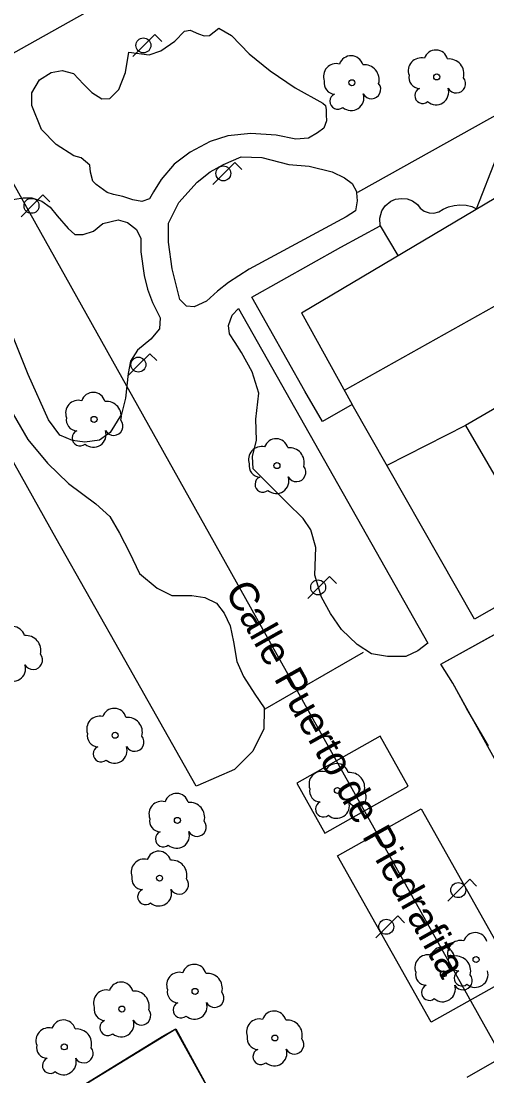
# Model space of a CAD drawing. Extents: x 282771 to 285132, y 4823109 to 4825496.
# Drawn here: x 283637.2 to 283677, y 4823316.2 to 4823406.2 of the extents above; entities that cross this region are included whole.
import ezdxf

# ---------------------------------------------------------------- set-up
doc = ezdxf.new("R2010")
doc.units = 0
for name, color, linetype in [('ACERA-INTERIOR', 7, 'Continuous'), ('ARBOL', 7, 'Continuous'), ('CALLE-EJE', 7, 'Continuous'), ('CALLE-TEXTO', 7, 'Continuous'), ('COLEGIO-AREA', 7, 'Continuous'), ('EDIFICIO', 7, 'Continuous'), ('FAROLA', 7, 'Continuous'), ('MEDIANERA', 7, 'Continuous'), ('PARQUE-JARDIN-AREA', 7, 'Continuous'), ('ZONA-VERDE', 7, 'Continuous')]:
    doc.layers.add(name, color=color, linetype=linetype)

msp = doc.modelspace()

# ---------------------------------------------------------------- linework, layer by layer
at = {"layer": 'ACERA-INTERIOR'}
for points in [[(283705.471, 4823369.905), (283686.968, 4823403.313), (283665.899, 4823391.566)], [(283658.036, 4823347.525), (283666.435, 4823352.366)]]:
    msp.add_lwpolyline(points, dxfattribs=at)
at = {"layer": 'ARBOL'}
for centre in [(283665.427, 4823400.948), (283672.673, 4823401.441), (283643.407, 4823372.22), (283659.026, 4823368.273), (283645.203, 4823345.261), (283664.193, 4823340.551), (283650.523, 4823338.001), (283649.003, 4823333.071), (283676.033, 4823326.126), (283673.243, 4823324.901), (283652.033, 4823323.411), (283645.783, 4823321.901), (283658.853, 4823319.431), (283640.863, 4823318.671)]:
    msp.add_circle(centre, 0.255, dxfattribs=at)
for centre, radius, start, end in [((283665.357, 4823402.208), 1.038, 15.64228, 161.38435), ((283671.343, 4823401.971), 1.097, 75.4318, 200.55608), ((283672.603, 4823402.701), 1.038, 15.64228, 161.38435), ((283673.733, 4823401.701), 1.272, 345.03273, 95.79925), ((283664.097, 4823401.478), 1.097, 75.4318, 200.55608), ((283666.487, 4823401.208), 1.272, 345.03273, 95.79925), ((283671.233, 4823401.401), 0.935, 168.59898, 268.13236), ((283674.343, 4823400.871), 0.797, 208.96246, 38.99103), ((283663.987, 4823400.908), 0.935, 168.59898, 268.13236), ((283667.097, 4823400.378), 0.797, 208.96246, 38.99103), ((283671.473, 4823399.851), 0.672, 113.73672, 309.4725), ((283672.613, 4823400.151), 1.086, 228.95447, 17.92796), ((283664.227, 4823399.358), 0.672, 113.73672, 309.4725), ((283665.367, 4823399.658), 1.086, 228.95447, 17.92796), ((283643.337, 4823373.48), 1.038, 15.64225, 161.38431), ((283642.077, 4823372.75), 1.097, 75.43176, 200.55605), ((283644.467, 4823372.48), 1.272, 345.0327, 95.79922), ((283641.967, 4823372.18), 0.935, 168.59894, 268.13232), ((283645.077, 4823371.65), 0.797, 208.96243, 38.99099), ((283642.207, 4823370.63), 0.672, 113.73669, 309.47246), ((283643.347, 4823370.93), 1.086, 228.95444, 17.92792), ((283658.956, 4823369.533), 1.038, 15.64225, 161.38431), ((283657.696, 4823368.803), 1.097, 75.43176, 200.55605), ((283660.086, 4823368.533), 1.272, 345.0327, 95.79922), ((283657.586, 4823368.233), 0.935, 168.59894, 268.13232), ((283660.696, 4823367.703), 0.797, 208.96243, 38.99099), ((283657.826, 4823366.683), 0.672, 113.73669, 309.47246), ((283658.966, 4823366.983), 1.086, 228.95444, 17.92792), ((283636.463, 4823353.501), 1.038, 15.64228, 161.38435), ((283637.593, 4823352.501), 1.272, 345.03273, 95.79925), ((283638.203, 4823351.671), 0.797, 208.96246, 38.99103), ((283636.473, 4823350.951), 1.086, 228.95447, 17.92796), ((283645.133, 4823346.521), 1.038, 15.64228, 161.38435), ((283643.873, 4823345.791), 1.097, 75.4318, 200.55608), ((283646.263, 4823345.521), 1.272, 345.03273, 95.79925), ((283643.763, 4823345.221), 0.935, 168.59898, 268.13236), ((283646.873, 4823344.691), 0.797, 208.96246, 38.99103), ((283644.003, 4823343.671), 0.672, 113.73672, 309.4725), ((283645.143, 4823343.971), 1.086, 228.95447, 17.92796), ((283664.123, 4823341.811), 1.038, 15.64228, 161.38435), ((283662.863, 4823341.081), 1.097, 75.4318, 200.55608), ((283665.253, 4823340.811), 1.272, 345.03273, 95.79925), ((283650.453, 4823339.261), 1.038, 15.64228, 161.38435), ((283662.753, 4823340.511), 0.935, 168.59898, 268.13236), ((283665.863, 4823339.981), 0.797, 208.96246, 38.99103), ((283649.193, 4823338.531), 1.097, 75.4318, 200.55608), ((283651.583, 4823338.261), 1.272, 345.03273, 95.79925), ((283662.993, 4823338.961), 0.672, 113.73672, 309.4725), ((283664.133, 4823339.261), 1.086, 228.95447, 17.92796), ((283649.083, 4823337.961), 0.935, 168.59898, 268.13236), ((283652.193, 4823337.431), 0.797, 208.96246, 38.99103), ((283649.323, 4823336.411), 0.672, 113.73672, 309.4725), ((283650.463, 4823336.711), 1.086, 228.95447, 17.92796), ((283647.673, 4823333.601), 1.097, 75.4318, 200.55608), ((283648.933, 4823334.331), 1.038, 15.64228, 161.38435), ((283650.063, 4823333.331), 1.272, 345.03273, 95.79925), ((283647.563, 4823333.031), 0.935, 168.59898, 268.13236), ((283650.673, 4823332.501), 0.797, 208.96246, 38.99103), ((283647.803, 4823331.481), 0.672, 113.73672, 309.4725), ((283648.943, 4823331.781), 1.086, 228.95447, 17.92796), ((283675.963, 4823327.386), 1.038, 15.64228, 161.38435), ((283674.703, 4823326.656), 1.097, 75.4318, 200.55608), ((283671.913, 4823325.431), 1.097, 75.4318, 200.55608), ((283673.173, 4823326.161), 1.038, 15.64228, 161.38435), ((283674.303, 4823325.161), 1.272, 345.03273, 95.79925), ((283651.963, 4823324.671), 1.038, 15.64228, 161.38435), ((283674.593, 4823326.086), 0.935, 168.59898, 268.13236), ((283650.703, 4823323.941), 1.097, 75.4318, 200.55608), ((283653.093, 4823323.671), 1.272, 345.03273, 95.79925), ((283671.803, 4823324.861), 0.935, 168.59898, 268.13236), ((283674.833, 4823324.536), 0.672, 113.73672, 309.4725), ((283674.913, 4823324.331), 0.797, 208.96246, 38.99103), ((283675.973, 4823324.836), 1.086, 228.95447, 17.92796), ((283645.713, 4823323.161), 1.038, 15.64228, 161.38435), ((283672.043, 4823323.311), 0.672, 113.73672, 309.4725), ((283673.183, 4823323.611), 1.086, 228.95447, 17.92796), ((283644.453, 4823322.431), 1.097, 75.4318, 200.55608), ((283646.843, 4823322.161), 1.272, 345.03273, 95.79925), ((283650.593, 4823323.371), 0.935, 168.59898, 268.13236), ((283653.703, 4823322.841), 0.797, 208.96246, 38.99103), ((283644.343, 4823321.861), 0.935, 168.59898, 268.13236), ((283650.833, 4823321.821), 0.672, 113.73672, 309.4725), ((283651.973, 4823322.121), 1.086, 228.95447, 17.92796), ((283647.453, 4823321.331), 0.797, 208.96246, 38.99103), ((283657.523, 4823319.961), 1.097, 75.4318, 200.55608), ((283658.783, 4823320.691), 1.038, 15.64228, 161.38435), ((283639.533, 4823319.201), 1.097, 75.4318, 200.55608), ((283640.793, 4823319.931), 1.038, 15.64228, 161.38435), ((283641.923, 4823318.931), 1.272, 345.03273, 95.79925), ((283644.583, 4823320.311), 0.672, 113.73672, 309.4725), ((283645.723, 4823320.611), 1.086, 228.95447, 17.92796), ((283659.913, 4823319.691), 1.272, 345.03273, 95.79925), ((283657.413, 4823319.391), 0.935, 168.59898, 268.13236), ((283660.523, 4823318.861), 0.797, 208.96246, 38.99103), ((283639.423, 4823318.631), 0.935, 168.59898, 268.13236), ((283642.533, 4823318.101), 0.797, 208.96246, 38.99103), ((283657.653, 4823317.841), 0.672, 113.73672, 309.4725), ((283658.793, 4823318.141), 1.086, 228.95447, 17.92796), ((283639.663, 4823317.081), 0.672, 113.73672, 309.4725), ((283640.803, 4823317.381), 1.086, 228.95447, 17.92796)]:
    msp.add_arc(centre, radius, start, end, dxfattribs=at)
at = {"layer": 'CALLE-EJE'}
msp.add_lwpolyline([(283707.963, 4823272.552), (283699.163, 4823280.432), (283690.733, 4823295.562), (283631.743, 4823400.83), (283648.803, 4823410.38)], dxfattribs=at)
at = {"layer": 'COLEGIO-AREA'}
msp.add_lwpolyline([(283643.713, 4823295.562), (283594.884, 4823267.882), (283586.328, 4823283.056), (283598.434, 4823289.912), (283607.724, 4823295.561), (283610.164, 4823297.042), (283634.083, 4823310.251), (283649.233, 4823319.561), (283650.343, 4823320.191), (283655.313, 4823311.182), (283643.713, 4823304.311), (283647.473, 4823297.692)], close=True, dxfattribs=at)
at = {"layer": 'EDIFICIO'}
for points in [[(283675.913, 4823355.161), (283665.453, 4823373.481), (283662.913, 4823372.031), (283661.423, 4823374.631), (283656.883, 4823382.661), (283664.493, 4823386.911), (283667.843, 4823388.741), (283667.813, 4823389.401), (283667.993, 4823390.001), (283668.283, 4823390.441), (283668.763, 4823390.831), (283669.153, 4823391.001), (283669.663, 4823391.081), (283670.153, 4823391.031), (283670.613, 4823390.861), (283671.033, 4823390.561), (283671.263, 4823390.251), (283671.603, 4823389.991), (283672.043, 4823389.841), (283672.433, 4823389.821), (283672.853, 4823389.931), (283673.233, 4823390.171), (283673.673, 4823390.361), (283674.153, 4823390.481), (283674.653, 4823390.531), (283675.183, 4823390.491), (283675.663, 4823390.371), (283676.073, 4823390.191), (283677.823, 4823394.621)], [(283684.503, 4823377.131), (283675.133, 4823371.701), (283682.553, 4823358.941), (283675.913, 4823355.161)], [(283643.713, 4823295.562), (283594.884, 4823267.882), (283586.328, 4823283.056), (283598.434, 4823289.912), (283607.724, 4823295.562), (283610.164, 4823297.042), (283634.083, 4823310.251), (283650.383, 4823320.211), (283655.313, 4823311.181), (283643.713, 4823304.311), (283647.473, 4823297.692), (283643.713, 4823295.562)]]:
    msp.add_lwpolyline(points, dxfattribs=at)
at = {"layer": 'FAROLA'}
for p, q in [((283648.602, 4823405.061), (283647.662, 4823404.131)), ((283649.192, 4823404.471), (283648.602, 4823405.061)), ((283647.662, 4823404.131), (283646.732, 4823403.191)), ((283655.429, 4823394.136), (283654.489, 4823393.206)), ((283656.019, 4823393.546), (283655.429, 4823394.136)), ((283654.489, 4823393.206), (283653.559, 4823392.266)), ((283639.043, 4823391.372), (283638.103, 4823390.442)), ((283639.633, 4823390.782), (283639.043, 4823391.372)), ((283638.103, 4823390.442), (283637.173, 4823389.502)), ((283648.176, 4823377.821), (283647.236, 4823376.891)), ((283648.766, 4823377.231), (283648.176, 4823377.821)), ((283647.236, 4823376.891), (283646.306, 4823375.951)), ((283663.527, 4823358.816), (283662.587, 4823357.886)), ((283664.117, 4823358.226), (283663.527, 4823358.816)), ((283662.587, 4823357.886), (283661.657, 4823356.946)), ((283675.493, 4823332.979), (283674.553, 4823332.049)), ((283676.083, 4823332.389), (283675.493, 4823332.979)), ((283674.553, 4823332.049), (283673.623, 4823331.109)), ((283669.343, 4823329.85), (283668.403, 4823328.92)), ((283669.933, 4823329.26), (283669.343, 4823329.85)), ((283668.403, 4823328.92), (283667.473, 4823327.98))]:
    msp.add_line(p, q, dxfattribs=at)
for centre, radius in [((283647.622, 4823404.131), 0.637), ((283654.449, 4823393.206), 0.637), ((283638.063, 4823390.442), 0.637), ((283647.196, 4823376.891), 0.637), ((283662.547, 4823357.886), 0.638), ((283674.513, 4823332.049), 0.637), ((283668.363, 4823328.92), 0.637)]:
    msp.add_circle(centre, radius, dxfattribs=at)
at = {"layer": 'MEDIANERA'}
for points in [[(283661.129, 4823381.324), (283679.403, 4823392.141), (283686.783, 4823378.601)], [(283667.843, 4823388.741), (283669.366, 4823386.199)], [(283683.263, 4823385.041), (283664.783, 4823374.681)], [(283661.129, 4823381.324), (283665.453, 4823373.481)], [(283675.133, 4823371.701), (283668.413, 4823368.271)]]:
    msp.add_lwpolyline(points, dxfattribs=at)
at = {"layer": 'PARQUE-JARDIN-AREA'}
msp.add_lwpolyline([(283673.016, 4823351.337), (283692.112, 4823361.891), (283695.705, 4823363.791), (283705.42, 4823369.648), (283711.066, 4823360.224), (283712.678, 4823357.034), (283721.874, 4823341.933), (283728.991, 4823329.472), (283734.01, 4823319.998), (283734.341, 4823318.909), (283734.496, 4823318.2), (283734.448, 4823316.672), (283734.381, 4823315.977), (283733.998, 4823315.113), (283733.521, 4823314.258), (283731.261, 4823311.352), (283717.427, 4823296.389), (283709.072, 4823287.491), (283696.313, 4823309.49), (283675.255, 4823347.535), (283674.062, 4823349.711)], close=True, dxfattribs=at)
at = {"layer": 'ZONA-VERDE'}
for p, q in [((283650.309, 4823404.497), (283651.119, 4823405.352)), ((283651.119, 4823405.352), (283651.622, 4823405.444)), ((283654.06, 4823405.595), (283655.149, 4823404.966)), ((283655.149, 4823404.966), (283656.667, 4823403.415)), ((283649.117, 4823403.673), (283650.309, 4823404.497)), ((283646.081, 4823401.816), (283646.363, 4823403.556)), ((283646.363, 4823403.556), (283648.111, 4823403.313)), ((283648.111, 4823403.313), (283649.117, 4823403.673)), ((283656.667, 4823403.415), (283658.459, 4823401.971)), ((283638.094, 4823400.077), (283638.751, 4823401.205)), ((283638.751, 4823401.205), (283639.738, 4823401.816)), ((283639.738, 4823401.816), (283640.678, 4823402.004)), ((283640.678, 4823402.004), (283641.664, 4823401.722)), ((283641.664, 4823401.722), (283642.51, 4823400.829)), ((283645.517, 4823400.359), (283646.081, 4823401.816)), ((283658.459, 4823401.971), (283660.571, 4823400.503)), ((283642.51, 4823400.829), (283643.215, 4823400.124)), ((283644.765, 4823399.607), (283645.517, 4823400.359)), ((283660.571, 4823400.503), (283662.951, 4823399.204)), ((283638.093, 4823398.993), (283638.094, 4823400.077)), ((283643.215, 4823400.124), (283644.061, 4823399.56)), ((283644.061, 4823399.56), (283644.765, 4823399.607)), ((283638.908, 4823396.949), (283638.093, 4823398.993)), ((283662.951, 4823399.204), (283663.17, 4823399.009)), ((283663.17, 4823399.009), (283663.226, 4823398.64)), ((283663.226, 4823398.64), (283663.243, 4823398.221)), ((283663.268, 4823397.701), (283663.033, 4823397.072)), ((283663.243, 4823398.221), (283663.268, 4823397.701)), ((283640.169, 4823395.672), (283638.908, 4823396.949)), ((283662.489, 4823396.661), (283661.734, 4823396.225)), ((283663.033, 4823397.072), (283662.489, 4823396.661)), ((283653.317, 4823395.922), (283651.602, 4823395.02)), ((283654.826, 4823396.408), (283653.317, 4823395.922)), ((283656.803, 4823396.601), (283654.826, 4823396.408)), ((283658.957, 4823396.484), (283656.803, 4823396.601)), ((283660.653, 4823396.133), (283658.957, 4823396.484)), ((283661.734, 4823396.225), (283660.653, 4823396.133)), ((283641.665, 4823394.704), (283640.169, 4823395.672)), ((283651.602, 4823395.02), (283650.263, 4823393.994)), ((283642.31, 4823394.527), (283641.665, 4823394.704)), ((283643.043, 4823393.912), (283642.31, 4823394.527)), ((283650.263, 4823393.994), (283649.131, 4823392.686)), ((283653.327, 4823393.347), (283654.455, 4823393.958)), ((283654.455, 4823393.958), (283655.958, 4823394.616)), ((283655.958, 4823394.616), (283657.744, 4823394.569)), ((283657.744, 4823394.569), (283660.046, 4823393.958)), ((283660.046, 4823393.958), (283661.784, 4823393.817)), ((283643.1, 4823393.313), (283643.043, 4823393.912)), ((283643.296, 4823392.56), (283643.1, 4823393.313)), ((283652.2, 4823392.454), (283653.327, 4823393.347)), ((283661.784, 4823393.817), (283663.758, 4823393.347)), ((283663.758, 4823393.347), (283664.791, 4823392.83)), ((283643.574, 4823392.253), (283643.296, 4823392.56)), ((283644.522, 4823391.587), (283643.574, 4823392.253)), ((283649.131, 4823392.686), (283648.494, 4823391.638)), ((283650.649, 4823390.714), (283652.2, 4823392.454)), ((283664.791, 4823392.83), (283665.449, 4823392.36)), ((283665.449, 4823392.36), (283665.825, 4823391.655)), ((283645.071, 4823391.398), (283644.522, 4823391.587)), ((283645.875, 4823391.245), (283645.071, 4823391.398)), ((283646.709, 4823390.967), (283645.875, 4823391.245)), ((283648.494, 4823391.638), (283648.142, 4823391.026)), ((283665.825, 4823391.655), (283665.832, 4823391.54)), ((283665.832, 4823391.54), (283665.872, 4823390.856)), ((283635.937, 4823390.9), (283637.347, 4823391.135)), ((283637.347, 4823391.135), (283638.099, 4823391.135)), ((283638.099, 4823391.135), (283638.944, 4823390.853)), ((283638.944, 4823390.853), (283639.649, 4823390.336)), ((283639.649, 4823390.336), (283640.26, 4823389.584)), ((283647.489, 4823390.808), (283646.709, 4823390.967)), ((283648.142, 4823391.026), (283647.489, 4823390.808)), ((283649.756, 4823388.975), (283650.649, 4823390.714)), ((283665.872, 4823390.856), (283665.731, 4823390.009)), ((283640.26, 4823389.584), (283641.2, 4823388.503)), ((283664.932, 4823389.492), (283656.663, 4823385.026)), ((283665.731, 4823390.009), (283664.932, 4823389.492)), ((283643.361, 4823388.267), (283644.16, 4823388.926)), ((283644.16, 4823388.926), (283645.475, 4823389.255)), ((283645.475, 4823389.255), (283646.274, 4823389.02)), ((283646.274, 4823389.02), (283647.026, 4823388.409)), ((283649.756, 4823387.33), (283649.756, 4823388.975)), ((283641.2, 4823388.503), (283641.763, 4823387.986)), ((283641.763, 4823387.986), (283642.468, 4823387.986)), ((283642.468, 4823387.986), (283643.361, 4823388.267)), ((283647.026, 4823388.409), (283647.401, 4823387.657)), ((283647.401, 4823387.657), (283647.401, 4823386.528)), ((283650.085, 4823385.073), (283649.756, 4823387.33)), ((283647.401, 4823386.528), (283647.683, 4823384.507)), ((283650.743, 4823382.441), (283650.085, 4823385.073)), ((283656.663, 4823385.026), (283654.877, 4823383.898)), ((283647.683, 4823384.507), (283647.965, 4823383.332)), ((283647.965, 4823383.332), (283648.388, 4823382.203)), ((283653.938, 4823383.146), (283652.998, 4823382.3)), ((283654.877, 4823383.898), (283653.938, 4823383.146)), ((283651.307, 4823381.877), (283650.743, 4823382.441)), ((283652.998, 4823382.3), (283651.964, 4823381.83)), ((283648.388, 4823382.203), (283649.046, 4823380.887)), ((283651.964, 4823381.83), (283651.307, 4823381.877)), ((283655.214, 4823381.12), (283655.731, 4823381.684)), ((283655.731, 4823381.684), (283671.905, 4823353.117)), ((283649.046, 4823380.887), (283648.999, 4823379.947)), ((283654.885, 4823380.227), (283655.214, 4823381.12)), ((283637.77, 4823376.045), (283636.36, 4823379.618)), ((283648.999, 4823379.947), (283648.247, 4823379.054)), ((283654.979, 4823379.521), (283654.885, 4823380.227)), ((283648.247, 4823379.054), (283647.119, 4823378.114)), ((283655.449, 4823378.769), (283654.979, 4823379.521)), ((283656.013, 4823377.923), (283655.449, 4823378.769)), ((283647.119, 4823378.114), (283646.509, 4823377.173)), ((283656.905, 4823376.278), (283656.013, 4823377.923)), ((283646.509, 4823377.173), (283646.32, 4823376.139)), ((283640.178, 4823362.068), (283631.888, 4823376.728)), ((283639.508, 4823372.19), (283637.77, 4823376.045)), ((283646.32, 4823376.139), (283646.086, 4823374.024)), ((283657.469, 4823374.444), (283656.905, 4823376.278)), ((283657.234, 4823372.235), (283657.469, 4823374.444)), ((283635.871, 4823373.744), (283637.75, 4823370.5)), ((283646.086, 4823374.024), (283645.757, 4823372.661)), ((283645.757, 4823372.661), (283644.77, 4823371.109)), ((283640.494, 4823370.874), (283639.508, 4823372.19)), ((283657.281, 4823370.449), (283657.234, 4823372.235)), ((283641.575, 4823370.404), (283640.494, 4823370.874)), ((283644.77, 4823371.109), (283643.877, 4823370.451)), ((283637.75, 4823370.5), (283639.442, 4823368.479)), ((283642.609, 4823370.263), (283641.575, 4823370.404)), ((283643.877, 4823370.451), (283642.609, 4823370.263)), ((283656.952, 4823369.038), (283657.281, 4823370.449)), ((283656.999, 4823368.004), (283656.952, 4823369.038)), ((283639.442, 4823368.479), (283641.227, 4823366.74)), ((283657.751, 4823367.252), (283656.999, 4823368.004)), ((283659.865, 4823365.137), (283657.751, 4823367.252)), ((283641.227, 4823366.74), (283643.571, 4823365.002)), ((283661.275, 4823363.773), (283659.865, 4823365.137)), ((283643.571, 4823365.002), (283644.746, 4823363.921)), ((283644.746, 4823363.921), (283645.592, 4823362.511)), ((283661.933, 4823362.786), (283661.275, 4823363.773)), ((283645.592, 4823362.511), (283646.437, 4823360.866)), ((283662.355, 4823361.282), (283661.933, 4823362.786)), ((283646.048, 4823351.698), (283640.178, 4823362.068)), ((283673.016, 4823351.337), (283692.112, 4823361.891)), ((283646.437, 4823360.866), (283647.283, 4823359.079)), ((283662.261, 4823358.931), (283662.355, 4823361.282)), ((283647.283, 4823359.079), (283648.787, 4823357.81)), ((283662.825, 4823357.051), (283662.261, 4823358.931)), ((283648.787, 4823357.81), (283650.055, 4823357.199)), ((283650.055, 4823357.199), (283651.747, 4823357.199)), ((283651.747, 4823357.199), (283652.874, 4823357.011)), ((283663.589, 4823355.655), (283662.825, 4823357.051)), ((283652.874, 4823357.011), (283653.861, 4823356.541)), ((283653.861, 4823356.541), (283654.519, 4823355.695)), ((283654.519, 4823355.695), (283655.036, 4823354.613)), ((283664.529, 4823354.292), (283663.589, 4823355.655)), ((283655.036, 4823354.613), (283655.317, 4823353.25)), ((283665.891, 4823353.023), (283664.529, 4823354.292)), ((283655.317, 4823353.25), (283655.599, 4823351.558)), ((283667.113, 4823352.224), (283665.891, 4823353.023)), ((283671.905, 4823353.117), (283671.059, 4823352.459)), ((283652.139, 4823340.923), (283646.048, 4823351.698)), ((283668.475, 4823351.989), (283667.113, 4823352.224)), ((283670.026, 4823351.989), (283668.475, 4823351.989)), ((283671.059, 4823352.459), (283670.026, 4823351.989)), ((283655.599, 4823351.558), (283656.163, 4823350.289)), ((283656.163, 4823350.289), (283657.15, 4823348.784)), ((283675.24, 4823347.512), (283674.062, 4823349.711)), ((283674.062, 4823349.711), (283674.062, 4823349.711)), ((283657.15, 4823348.784), (283657.948, 4823347.609)), ((283657.946, 4823347.504), (283657.901, 4823345.823)), ((283657.948, 4823347.609), (283657.946, 4823347.504)), ((283677.105, 4823344.371), (283675.24, 4823347.512)), ((283657.901, 4823345.823), (283656.962, 4823343.895)), ((283656.962, 4823343.895), (283655.411, 4823342.344)), ((283655.411, 4823342.344), (283652.263, 4823340.981)), ((283652.263, 4823340.981), (283652.139, 4823340.923)), ((283664.204, 4823334.979), (283671.335, 4823338.996)), ((283671.335, 4823338.996), (283679.339, 4823324.784)), ((283672.209, 4823320.768), (283664.204, 4823334.979)), ((283679.339, 4823324.784), (283672.209, 4823320.768)), ((283672.209, 4823320.768), (283672.209, 4823320.768)), ((283675.27, 4823316.096), (283681.873, 4823319.871))]:
    msp.add_line(p, q, dxfattribs=at)
for points in [[(283651.622, 4823405.444), (283652.322, 4823405.122), (283652.82, 4823404.935), (283653.27, 4823404.964), (283654.06, 4823405.595)], [(283674.062, 4823349.711), (283673.016, 4823351.337)], [(283667.844, 4823345.194), (283660.713, 4823341.177), (283663.119, 4823336.905), (283670.25, 4823340.922), (283667.844, 4823345.194)]]:
    msp.add_lwpolyline(points, dxfattribs=at)

# ---------------------------------------------------------------- texts
at = {"layer": 'CALLE-TEXTO'}
msp.add_text('Calle Puerto de Piedrafita', height=2.5, rotation=299.26495, dxfattribs=at).set_placement((283654.543, 4823357.587))

doc.saveas('drawing.dxf')
